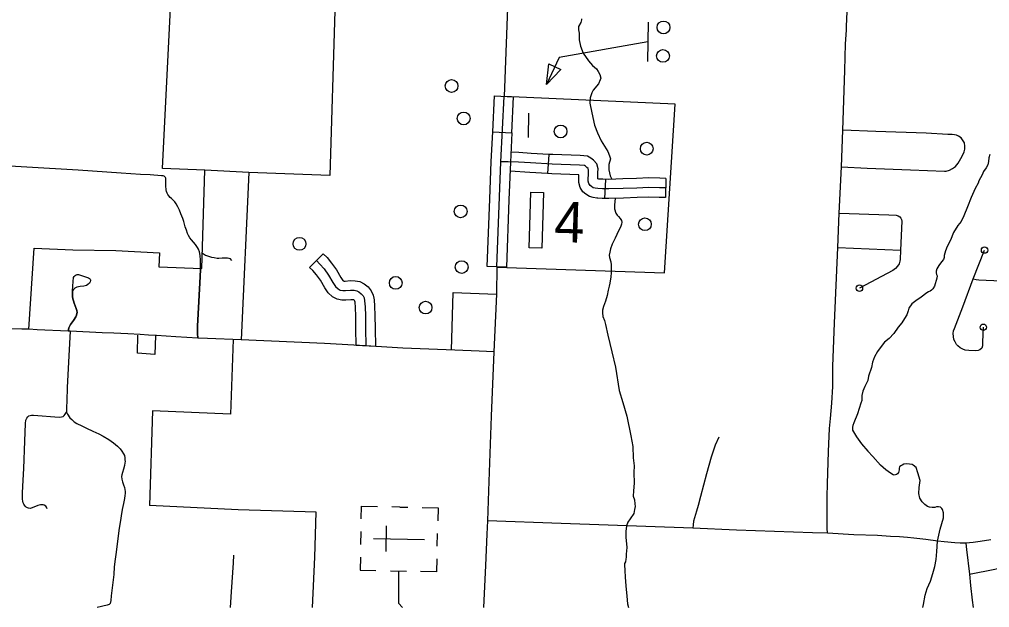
# Model space of a CAD drawing. Extents: x 653372 to 905732, y 627442 to 787275.
# Drawn here: x 658495 to 666097, y 728634 to 733242 of the extents above; entities that cross this region are included whole.
import ezdxf

# ---------------------------------------------------------------- set-up
doc = ezdxf.new("R2010")
doc.units = 0
for name, color, linetype in [('31', 7, 'Continuous'), ('32', 7, 'Continuous'), ('33', 7, 'Continuous'), ('34', 7, 'Continuous'), ('35', 7, 'Continuous'), ('56', 7, 'Continuous'), ('57', 7, 'Continuous'), ('6', 7, 'Continuous')]:
    doc.layers.add(name, color=color, linetype=linetype)

msp = doc.modelspace()

# ---------------------------------------------------------------- linework, layer by layer
at = {"layer": '31'}
for p, q in [((662203.2, 732361.1), (662353.1, 732353.7)), ((660768.9, 731299.1), (660874.2, 731405.9)), ((662310.6, 731299.5), (662160.7, 731305.1))]:
    msp.add_line(p, q, dxfattribs=at)
for points in [[(662203.2, 732361.1), (662217.1, 732642.4), (662366.9, 732635)], [(662235.6, 731302.3), (662266.7, 732126.2), (662292, 732638.7)], [(662353.1, 732353.7), (662366.9, 732635)], [(662180.6, 731832.8), (662191.8, 732129.4), (662203.2, 732361.1)], [(662353.1, 732353.7), (662341.7, 732122.9), (662330.5, 731827.1)], [(662160.7, 731305.1), (662180.6, 731832.8)], [(662330.5, 731827.1), (662310.6, 731299.5)], [(660874.2, 731405.9), (660905.1, 731375.5), (660941.4, 731332), (660978.8, 731279.2), (661013.8, 731220.5), (661029.9, 731197.1), (661034.5, 731192.7), (661037.7, 731192.1), (661046.9, 731191.8), (661086.6, 731195.8), (661126.5, 731194.6), (661162.4, 731187.8), (661196.8, 731170.4), (661227, 731145.4), (661251.1, 731116.1), (661268, 731082), (661271.8, 731056.4)], [(660821.6, 731352.5), (660849.8, 731324.6), (660882, 731286.2), (660915.9, 731238.3), (660950.6, 731180), (660972.5, 731148.2), (660991.7, 731129.9), (661009.1, 731121), (661029.8, 731117.3), (661049.6, 731116.7), (661089.2, 731120.7), (661118.3, 731119.8), (661138, 731116.1), (661155.4, 731107.3), (661173.7, 731092.2), (661187.7, 731075.1), (661195.6, 731059.3), (661199, 731036.3), (661202.8, 730989.3), (661205.9, 730919.5), (661207.1, 730819.6), (661209.2, 730683.2)], [(661123.5, 731034.1), (661123.3, 731035.3), (661120.3, 731039), (661114, 731044.2), (661113.6, 731044.4), (661110.2, 731045.1), (661091.9, 731045.6), (661052.2, 731041.6), (661022, 731042.5), (660985, 731049.2), (660948, 731068), (660915.2, 731099.2), (660887.4, 731139.6), (660853, 731197.4), (660822.5, 731240.3), (660794.6, 731273.7), (660768.9, 731299.1)], [(661284.3, 730679.1), (661134.1, 730687.7), (661132.1, 730818.5), (661131, 730917.4), (661128, 730984.6), (661124.5, 731027.6), (661123.5, 731034.1)], [(661271.8, 731056.4), (661273.6, 731044.9), (661277.7, 730994), (661280.9, 730921.6), (661282.1, 730820.6), (661284.3, 730679.1)], [(660232.2, 730731.2), (659967.6, 730742), (659891.8, 730743.4), (659720.5, 730755.4), (659568.9, 730764.7), (659506.7, 730768.6), (659442.2, 730772.5), (659343.4, 730778.2), (659233.7, 730782.8), (659143.5, 730786.8), (658891.9, 730798.9), (658878.1, 730799.4), (658634.6, 730810.8), (658567.9, 730814.7)], [(660172.2, 729043.6), (660169.4, 728984.5), (660153.9, 728757.6), (660147.4, 728633.5)]]:
    msp.add_lwpolyline(points, dxfattribs=at)
at = {"layer": '32'}
for p, q in [((662642.2, 732184.3), (662634, 732034.5)), ((663086.5, 731988.6), (663078.6, 731838.8)), ((663559.5, 731996.2), (663557.9, 731846.2))]:
    msp.add_line(p, q, dxfattribs=at)
for points in [[(662642.2, 732184.3), (662503.5, 732191.9), (662408, 732199), (662345.5, 732200.3)], [(663035, 731990.5), (663034.4, 731990.5), (663027.5, 731991.6), (663027.8, 732043.4), (663028.6, 732069.9), (663018.2, 732111), (662992.4, 732138.4), (662972.5, 732153.6), (662946.8, 732168.9), (662888, 732174.4), (662673.5, 732182.5), (662642.2, 732184.3)], [(663558.7, 731921.2), (663510.3, 731921.7), (663427.1, 731924.2), (663333.5, 731920.2), (663226.3, 731916.6), (663113.2, 731913.2), (663063.9, 731913.9), (663026.5, 731915.8), (663006.8, 731919), (662991.7, 731922.8), (662978.3, 731931.7), (662966.7, 731941.4), (662957, 731956.2), (662952.4, 731974.2), (662952.8, 732044.7), (662953.3, 732061.7), (662950.3, 732073.7), (662942.1, 732082.4), (662930.4, 732091.3), (662922.9, 732095.8), (662883.1, 732099.5), (662670, 732107.6), (662498.6, 732117), (662404.5, 732124.1), (662324.6, 732125.6), (662266.7, 732126.2)], [(662634, 732034.5), (662493.7, 732042.2), (662339.1, 732053.8)], [(663027.1, 731840.7), (663018.6, 731841.1), (662991.7, 731845.4), (662960.7, 731853.3), (662933.3, 731871.6), (662910.2, 731890.9), (662887.4, 731925.4), (662877.3, 731965), (662877.7, 732024.7), (662666.5, 732032.7), (662634, 732034.5)], [(663559.5, 731996.2), (663511.8, 731996.7), (663426.6, 731999.2), (663330.6, 731995.2), (663223.9, 731991.6), (663112.5, 731988.2), (663066.3, 731988.8), (663035, 731990.5)], [(663557.9, 731846.2), (663508.8, 731846.7), (663427.6, 731849.2), (663336.3, 731845.3), (663228.7, 731841.7), (663113.8, 731838.2), (663061.4, 731838.9), (663027.1, 731840.7)], [(659913.2, 731291.4), (659912.9, 731280.1), (659908.8, 731177.6), (659895.5, 730933.7), (659890.6, 730839.2), (659890.9, 730781.3), (659891.8, 730743.4)], [(658910.4, 731115.1), (658909.7, 731106.3), (658910.2, 731070.9), (658913.1, 731051.9), (658917.6, 731037), (658924, 731018.4), (658940.2, 730977), (658945.7, 730959.9), (658946.8, 730946.4), (658946, 730938.5), (658942.7, 730925.1), (658936.8, 730911.8), (658918.4, 730882), (658894.1, 730851.3), (658882.4, 730825.2), (658879.5, 730811.9), (658878.1, 730799.4)]]:
    msp.add_lwpolyline(points, dxfattribs=at)
at = {"layer": '33'}
for points in [[(662422.3, 735934.1), (662422, 735910.3), (662423.9, 735879.1), (662419.7, 735786.8), (662405.4, 735404), (662405.2, 735350), (662401.3, 735272.3), (662387, 734955.8), (662374, 734640.8), (662353.4, 734259.6), (662326.9, 733566.5), (662319.2, 733332.9), (662292, 732638.7)], [(664948.1, 732373.3), (664961.4, 732841.6), (664969, 733050.4), (664974.7, 733157.7), (664975.3, 733173.2), (664976.2, 733188.7), (664981.7, 733300), (664987.2, 733447.3), (664989.1, 733516.1), (664993.2, 733582.7), (664999.8, 733714.4), (665006.6, 733875.6), (665025.1, 734116.6), (665035.4, 734305.6), (665037.6, 734339.8), (665045.2, 734520.9), (665052.7, 734770), (665059.8, 734837.5), (665062, 734970.5), (665063, 735025.3), (665065.2, 735226.5), (665092.8, 735824.2)], [(664826.9, 729216.4), (664824.8, 729256.1), (664822.9, 729350.1), (664823.6, 729504.2), (664825.9, 729604), (664833.5, 729856.4), (664843.5, 730035.4), (664849.9, 730115.2), (664860.8, 730234.9), (664867.3, 730364.4), (664869.5, 730525.9), (664882.8, 730860.6), (664908.1, 731453.4), (664918.5, 731723.6), (664935.5, 732085.3), (664948.1, 732373.3)], [(664935.5, 732085.3), (665137.5, 732076.6), (665475.9, 732061.8), (665742.3, 732052.5), (665756.3, 732053.4), (665781.6, 732060.6), (665807.1, 732073), (665829.4, 732089.5), (665850.7, 732116), (665882.1, 732171.3), (665897, 732204.6), (665902.2, 732225.6), (665902.2, 732247.4), (665899.1, 732274), (665891, 732290.7), (665873.2, 732313.3), (665853.8, 732327.8), (665837.4, 732334.7), (665821, 732337.8), (665803.2, 732339), (665770.2, 732340.7), (665599.9, 732349.7)], [(665599.9, 732349.7), (665206.6, 732363.5), (664948.1, 732373.3)], [(659759.6, 731718.8), (659749.3, 731747.2), (659737.2, 731773.3), (659723.3, 731795.9), (659712.1, 731812.6), (659699.1, 731825.9), (659686, 731837.4), (659675.7, 731846.5), (659665, 731859.1), (659656.6, 731871), (659651.6, 731880), (659647.3, 731892.4), (659645.9, 731905.3), (659642.8, 731936.9), (659643, 731983.1), (659641.6, 731997.8), (659638.5, 732004), (659631.2, 732010.1), (659627.9, 732012.2), (659620.5, 732015.4), (659608.9, 732016.3), (659519.1, 732023.7), (659444.1, 732027.4), (659292.1, 732037.2), (658956, 732059.3), (658553, 732084.3), (658287.5, 732100.7)], [(664918.5, 731723.6), (665306, 731710.2), (665365.3, 731707.1), (665381.1, 731703.3), (665393.4, 731695.7), (665401.7, 731685.5), (665407.3, 731673.4), (665409.5, 731660.8), (665398.8, 731435), (665395.9, 731359.4), (665394.2, 731346.9), (665387, 731327.3), (665374.5, 731307.8), (665359.4, 731291), (665338.4, 731275.1), (665077.1, 731136.2)], [(664908.1, 731453.4), (665398.8, 731435)], [(666047.3, 730829.8), (666042.4, 730713.9), (666040, 730683.1), (666035.1, 730667.1), (666021.5, 730653.6), (666007.3, 730646.6), (665988.9, 730644.3), (665933.9, 730647.4), (665905.4, 730651.2), (665887.2, 730657.6), (665867, 730669.2), (665849, 730683), (665836.9, 730695.1), (665825.8, 730714.5), (665817.5, 730733.9), (665813.1, 730758.3), (665811.6, 730779.6), (665814.4, 730801.6), (665821.6, 730821.2), (665886.9, 730989.6), (665969.1, 731208.6), (666057.4, 731434.2)], [(662235.7, 731302.3), (662232.1, 731088.5), (662213.5, 730636.5), (662192.1, 730132.4), (662170.3, 729548.2), (662162.5, 729312.2), (662157.1, 729209.5), (662145.9, 728963), (662130.1, 728633.5)], [(665969.1, 731208.6), (665991.7, 731204.1), (666012.2, 731200.5), (666421, 731181.8)], [(658567.9, 730814.7), (658561.7, 730815), (658514.2, 730815.8), (658408.5, 730816.9), (658264.6, 730817.2), (658232.4, 730814.9)], [(660232.2, 730731.2), (659967.6, 730742), (659891.8, 730743.4), (659720.5, 730755.4), (659568.9, 730764.7), (659506.7, 730768.6), (659442.2, 730772.5), (659343.4, 730778.2), (659233.7, 730782.8), (659143.5, 730786.8), (658891.9, 730798.9), (658878.1, 730799.4), (658634.6, 730810.8), (658567.9, 730814.7)], [(658891.9, 730798.9), (658880.9, 730605.8), (658868.7, 730358.9), (658865.5, 730253.2), (658863.4, 730200.9), (658862.9, 730182.7), (658863.3, 730163.5), (658871.4, 730147.9), (658890.3, 730120.9), (658905.2, 730106.1), (658923.4, 730089.7), (658945.1, 730076.1), (658983.8, 730056.2), (659020.7, 730038.8), (659069.5, 730016.2), (659117.2, 729994.2), (659150.6, 729975.6), (659195.4, 729949.8), (659232.5, 729923.8), (659262.9, 729898.4), (659285.3, 729877.5), (659298.6, 729857.9), (659311.5, 729838.4), (659317.3, 729823.8), (659320.1, 729806.9), (659322, 729791), (659323.1, 729778.5), (659320.8, 729766.6), (659318.3, 729747.7), (659309.7, 729716.8), (659302.3, 729691.6), (659296.9, 729673.5), (659295.6, 729660.1), (659298.3, 729640.4), (659302.5, 729619.6), (659310.4, 729595.8), (659317.9, 729574.5), (659320.3, 729557.6), (659323.2, 729543.2), (659322.3, 729528.3), (659321.2, 729510.8), (659317.2, 729488.4), (659309.2, 729447.8), (659299.7, 729401.6), (659292, 729352.8), (659287.1, 729316.5), (659276.6, 729255.3), (659264, 729153.9), (659252.2, 729066.9), (659244.4, 729014), (659238.3, 728953.7), (659234.1, 728893.4), (659214.7, 728726.9), (659212.1, 728689)], [(662213.5, 730636.5), (662096.8, 730641.2), (661907.7, 730649.6), (661498.4, 730667.2), (661205.7, 730683.4), (660886.1, 730702.4), (660232.2, 730731.2)], [(665824.2, 729141.8), (665741.2, 729148.7), (665691.4, 729153.9), (665596.4, 729166.3), (665504.2, 729178.6), (665453, 729183.8), (665391.4, 729187.8), (665319.8, 729190.4), (665218.4, 729197.4), (665033.2, 729204.5), (664826.9, 729216.4), (664708.4, 729219.4), (664410.9, 729229), (664114, 729240.9), (663772.7, 729257), (662738.9, 729291.2), (662162.5, 729312.2)], [(665938.6, 728894.2), (666136.6, 728935.3), (666359.5, 728984.4), (666507.3, 729016), (666646.1, 729041.2), (666697.2, 729053.6), (666725.3, 729063.1), (666747.7, 729074.2), (666785, 729092.9), (666809.4, 729107.1), (666848.9, 729125.8), (666896, 729144.4), (666947.5, 729155.1), (667027.8, 729165.9), (667195.5, 729188.8), (667527.3, 729233.2), (667706.9, 729259.4), (667955.2, 729293.8), (668049.7, 729310.1), (668096.3, 729319.7)], [(666105.4, 729163.5), (666023.5, 729151.2), (665968.9, 729143.3), (665910, 729138.5), (665866.7, 729139), (665824.2, 729141.8)], [(665910, 729138.5), (665916.9, 729088), (665938.6, 728894.2), (665947.4, 728807.2), (665960, 728691.1), (665967, 728633.5)], [(660172.2, 729043.6), (660169.4, 728984.5), (660153.9, 728757.6), (660147.4, 728633.5)], [(659212.1, 728689), (659207, 728666.4), (659199.3, 728658), (659182.4, 728653.5), (659104.7, 728633.5)]]:
    msp.add_lwpolyline(points, dxfattribs=at)
for centre in [(666057.4, 731434.2), (665077.1, 731136.2), (666047.3, 730829.8)]:
    msp.add_circle(centre, 25, dxfattribs=at)
at = {"layer": '34'}
for points in [[(659913.2, 731291.4), (659914.6, 731321.4), (659913.3, 731357.1), (659911.7, 731390.2), (659909.5, 731407.5), (659905.5, 731420.2), (659897.4, 731442.4), (659891.1, 731454), (659873.4, 731478.5), (659844.1, 731515), (659831.1, 731531.2), (659819.4, 731548.5), (659811.1, 731564), (659803.1, 731590.5), (659793.9, 731617.1), (659783.5, 731657.3), (659774.9, 731682.7), (659759.6, 731718.8)], [(659928.8, 731410.9), (659951.7, 731394.6), (659977.3, 731385.8), (659999.5, 731378.7), (660020.3, 731375.1), (660043.2, 731371.9), (660057.6, 731370), (660084.1, 731373.2), (660108, 731374.4), (660125, 731374.4), (660135.3, 731371.6), (660144.7, 731367.4), (660157.4, 731353)], [(658910.4, 731115.1), (658915.7, 731187.4), (658919.6, 731218.7), (658924.3, 731228), (658931.5, 731235.3), (658940.2, 731241), (658947.7, 731243.7), (658958.7, 731242.4), (659036.1, 731216.2), (659043.9, 731212), (659049.8, 731207.3), (659052.1, 731201.7), (659053, 731196.7), (659049.6, 731184.9), (659043.3, 731175.1), (659031, 731164), (659020.9, 731157.8), (659009.8, 731153.2), (658998.3, 731151.5), (658970.8, 731147.9), (658944.2, 731143.7), (658928.6, 731136.7), (658918.8, 731126.5), (658910.4, 731115.1)], [(659891.8, 730743.4), (659890.9, 730781.3), (659890.6, 730839.2), (659895.5, 730933.7), (659908.8, 731177.6), (659912.9, 731280.1), (659913.2, 731291.4)], [(658878.1, 730799.4), (658879.5, 730811.9), (658882.4, 730825.2), (658894.1, 730851.3), (658918.4, 730882), (658936.8, 730911.8), (658942.7, 730925.1), (658946, 730938.5), (658946.8, 730946.4), (658945.7, 730959.9), (658940.2, 730977), (658924, 731018.4), (658917.6, 731037), (658913.1, 731051.9), (658910.2, 731070.9), (658909.7, 731106.3), (658910.4, 731115.1)], [(658711.5, 729406.3), (658706.7, 729421.4), (658700.6, 729427.8), (658689.8, 729435.8), (658679.8, 729439), (658667.9, 729439.8), (658659.2, 729439.1), (658637.9, 729433.5), (658606.8, 729419.6), (658586, 729412), (658577.8, 729410.8), (658566.3, 729411.7), (658558.2, 729413.8), (658547.3, 729419.9), (658539.4, 729427.8), (658533.4, 729435.7), (658528.9, 729444), (658524.4, 729455.2), (658521.4, 729468.2), (658520, 729483.6), (658518.3, 729507.2), (658519, 729529.2), (658522.5, 729583.8), (658529.1, 729723.9), (658537, 729937.9), (658542.1, 730075.7), (658545.7, 730101.5), (658552.4, 730116.7), (658560.9, 730128.4), (658569.8, 730135.8), (658579, 730139.4), (658590.1, 730140.5), (658604.9, 730140.1), (658806, 730125.4), (658823.8, 730127.7), (658836.9, 730130.7), (658844.8, 730138.1), (658854.2, 730149.8), (658863.3, 730163.5)], [(663975.4, 729968.4), (663947.7, 729906.1), (663914.1, 729811.7), (663879.5, 729681.7), (663830.5, 729503.6), (663813, 729432.9), (663799.5, 729388), (663777, 729311.9), (663772.9, 729282.1), (663772.7, 729257)]]:
    msp.add_lwpolyline(points, dxfattribs=at)
at = {"layer": '35'}
for points in [[(662899.2, 733245.8), (662899.8, 733237.2), (662892.8, 733217.5), (662876.6, 733186.5), (662876.7, 733160.1), (662881, 733132.8), (662881.1, 733082.6), (662892.4, 733031.3), (662912, 732977.1), (662954.4, 732918), (662984.7, 732879.7), (663015.4, 732854.2), (663030.1, 732834.2), (663042.1, 732810), (663050.6, 732782.5)], [(663050.6, 732782.5), (663044.2, 732767), (663032.2, 732736.8), (662991.7, 732687.8), (662979.9, 732665.2), (662966.9, 732627.4), (662965.7, 732586.6), (662981.2, 732509.6), (663001.3, 732413.8), (663024.9, 732351.9), (663052, 732290.4), (663080.5, 732248.7), (663105.6, 732208), (663119.8, 732172.7), (663125.1, 732149.6), (663112.7, 732104), (663114, 732062.3), (663124.5, 732016.1), (663135.6, 731988.9)], [(666097.5, 732183), (666092.1, 732156.4), (666088.2, 732128.2), (666082.9, 732102.4), (666069.2, 732079.9), (666048.4, 732049.9), (666037.7, 732022.7), (666012.6, 731977.6), (666006.7, 731958.4), (665984.8, 731917.7), (665952.9, 731847.6), (665922.4, 731772), (665895.8, 731701.7), (665873.8, 731657.3), (665848.5, 731627.5), (665814.7, 731571.1), (665789.9, 731511.5), (665764.4, 731461.8), (665750.4, 731428.5), (665740.9, 731392.9), (665740.4, 731376.1), (665736.8, 731360.1), (665720.3, 731343), (665698.7, 731313.1), (665684.2, 731286.8), (665679.1, 731270.1), (665679.4, 731255.6), (665681.3, 731242.5), (665686.4, 731231.6), (665683.5, 731214.1), (665664.9, 731152.8), (665652.8, 731131.7), (665642.5, 731120.6), (665632.3, 731111.7), (665618.4, 731107.5), (665605.2, 731099.5), (665560, 731065.4), (665520.1, 731036), (665488.1, 731013.2), (665463.4, 730978.8), (665459.7, 730957.5), (665448, 730926.5), (665431.1, 730898), (665408.7, 730865), (665380.2, 730830.7), (665346.2, 730779.7), (665309.8, 730741.1), (665272.7, 730712.3), (665254.8, 730690), (665218.9, 730640.6), (665195.5, 730598.5), (665180.5, 730556.1), (665170.8, 730515.1)], [(663162, 731839.7), (663156.7, 731788), (663158.4, 731757.3), (663169.3, 731723.8), (663177.3, 731707.4), (663188.9, 731697.7), (663202.8, 731681.2), (663212.5, 731665.6), (663215.6, 731652.7), (663213.4, 731637.5), (663204.2, 731613.1), (663189.7, 731585.5)], [(663189.7, 731585.5), (663162.3, 731528), (663138.7, 731480.2), (663126.8, 731443), (663120.7, 731417.9), (663116.7, 731395.5), (663118.6, 731375.1), (663127.7, 731341.7), (663131.3, 731318.1), (663131.3, 731287.6), (663132, 731256), (663127.7, 731225.5), (663120.2, 731175.6), (663116.1, 731151.2), (663109.2, 731119.9), (663101.2, 731079.4), (663087.4, 731034.9), (663072.5, 730991.2), (663064.9, 730964.2), (663062.5, 730943), (663065.1, 730914.9), (663078.6, 730883), (663086.1, 730851.3), (663106.5, 730766.8), (663135.8, 730636.7), (663164.4, 730516), (663195.5, 730334.4), (663223.3, 730240.9), (663254.9, 730132.8), (663285.7, 729979.2), (663300.2, 729894.6), (663302.7, 729807.9), (663311.8, 729743.8), (663310.2, 729690.7), (663311.1, 729607.4), (663306.8, 729548.8), (663304.7, 729507.3), (663313.2, 729477.2), (663316.5, 729447.4), (663318.4, 729426.1), (663315.1, 729401.7), (663309.1, 729369.5), (663281.5, 729329.6), (663262.9, 729302.1), (663252.6, 729273.5)], [(665170.8, 730515.1), (665148.9, 730447), (665142.5, 730413.5), (665118.2, 730365.3), (665104.1, 730328.3), (665096.9, 730294.8), (665095.8, 730255.9), (665088.3, 730234.7), (665060.6, 730152.7), (665034, 730080.9), (665024.9, 730060.5), (665021.5, 730047.6), (665021.6, 730036.2), (665022.3, 730022.3), (665054.3, 729970.9), (665094, 729916.2), (665142.3, 729859.2)], [(665572.9, 728633.5), (665577.8, 728657.4), (665592.1, 728730.3), (665608.5, 728781.8), (665632.6, 728841.5), (665651, 728900.4), (665668.5, 728955.6), (665677.5, 729010.1), (665684.1, 729073), (665689.3, 729153.7), (665710.7, 729247.8), (665734.7, 729336.3), (665736.8, 729375.2), (665728.3, 729402.4), (665723, 729410.9), (665712.1, 729419.6), (665697.4, 729423.7), (665681.6, 729423.3), (665666.6, 729418.2), (665647, 729416.9), (665626.7, 729419.4), (665610.2, 729426.4), (665589.3, 729441.8), (665567.7, 729462.9), (665550.9, 729490.4), (665543.6, 729526.8), (665544.1, 729573.2), (665552.2, 729629.6), (665534.6, 729689.6), (665521.8, 729729.9), (665499.2, 729749.1), (665489.2, 729755), (665469.8, 729757.5), (665445.7, 729760), (665426.1, 729756), (665411, 729749.9), (665401.6, 729744.6), (665392, 729735.6), (665388.1, 729726.5), (665388.6, 729712.5), (665382.4, 729691.4), (665375.6, 729682.3), (665366.1, 729675.1), (665348.3, 729671), (665340.1, 729674.1), (665320, 729685.8), (665283.7, 729712), (665243, 729749.4), (665181.9, 729818.1), (665142.3, 729859.2)], [(663252.6, 729273.5), (663245.5, 729230.8), (663246.8, 729186.2), (663253.3, 729104.2), (663249.9, 729051.8), (663249.2, 729027.8), (663247, 729012.7), (663242.8, 728993.3), (663237, 728978.3), (663234.9, 728967.7), (663238, 728923.1), (663241, 728872.3), (663246, 728803.6), (663255.2, 728723.3), (663260.4, 728661.7), (663267.4, 728633.5)]]:
    msp.add_lwpolyline(points, dxfattribs=at)
at = {"layer": '56'}
for p, q in [((662625.7, 732732.8), (662644.1, 732893)), ((662736.6, 732849.9), (662625.7, 732732.8)), ((662644.1, 732893), (662736.6, 732849.9))]:
    msp.add_line(p, q, dxfattribs=at)
for points in [[(663421.6, 733219.2), (663416.2, 732911.2)], [(663418.9, 733065.2), (662724, 732943.5), (662625.7, 732732.8)], [(662483.7, 732507.7), (662481.7, 732315.2)]]:
    msp.add_lwpolyline(points, dxfattribs=at)
msp.add_lwpolyline([(662502, 731889.4), (662601.9, 731886.4), (662588.8, 731449.1), (662488.8, 731452.1)], close=True, dxfattribs=at)
for centre in [(663541.6, 733178.3), (663537.4, 732955.8), (661881, 732720), (661975.7, 732465.6), (662735.2, 732363.6), (663410.5, 732228.9), (661952.1, 731737.5), (663395.9, 731636.7), (660689.5, 731483.3), (661960.3, 731301.1), (661443.7, 731177.6), (661677.6, 730983.7)]:
    msp.add_circle(centre, 50, dxfattribs=at)
at = {"layer": '57'}
for p, q in [((661475.2, 729421), (661413.6, 729422.4)), ((661475.2, 729421), (661538.6, 729419.6)), ((661367.3, 729073.4), (661371.8, 729274.3)), ((661170.7, 729228.5), (661168.5, 729128.5)), ((661768.3, 729114.8), (661770.6, 729214.8)), ((661269.6, 729175.7), (661669.5, 729166.6)), ((661469.5, 729171.1), (661469.5, 729171.1)), ((661469.5, 729171.1), (661469.5, 729171.1)), ((661402.2, 728922.6), (661527.2, 728919.7))]:
    msp.add_line(p, q, dxfattribs=at)
for points in [[(661173, 729327.9), (661175.3, 729427.9), (661300.2, 729425)], [(661650.1, 729417.1), (661775.1, 729414.2), (661772.8, 729314.3)], [(661166.2, 729028), (661163.9, 728928), (661288.9, 728925.1)], [(661766, 729014.3), (661763.7, 728914.4), (661638.8, 728917.2)], [(661464.7, 728921.2), (661465.7, 728668.6), (661495.6, 728633.5)]]:
    msp.add_lwpolyline(points, dxfattribs=at)
at = {"layer": '6'}
for points in [[(660967.1, 733307.7), (660928.4, 732019.4), (660291.3, 732042), (659948.9, 732059.3), (659616.3, 732073.5), (659682.4, 733381.4), (659703.8, 734056.5), (659720.1, 734471.5), (659729.1, 734736.3), (660934.1, 734692.5), (662372.8, 734619.5)], [(662235.6, 731301.2), (663549.8, 731257.2), (663633.7, 732578.7), (662292, 732638.7)], [(658567.9, 730813.9), (658610.2, 731450.2), (658913.2, 731436.7), (659250.2, 731430.1), (659592.5, 731412.6), (659587.9, 731303.2), (659925, 731290.9), (659948.9, 732059.3)], [(660291.3, 732042), (660232.2, 730731.2)], [(661880.4, 730650.8), (661893.8, 731101.2), (662232, 731088.5)], [(659556.7, 730615.9), (659420.9, 730627.6), (659423.1, 730768)], [(660169.1, 730733.8), (660149.1, 730150.1), (659538.6, 730174.7), (659514.4, 729432.8)], [(659560.5, 730765.2), (659556.7, 730615.9)], [(660791.8, 728633.5), (660809.4, 729029.8), (660820.9, 729381.9), (660209.1, 729398.8), (659514.4, 729432.8)]]:
    msp.add_lwpolyline(points, dxfattribs=at)

# ---------------------------------------------------------------- texts
at = {"layer": '56'}
msp.add_text('4', height=316.8, rotation=358.28003, dxfattribs=at).set_placement((662682.2, 731498.7))

doc.saveas('drawing.dxf')
